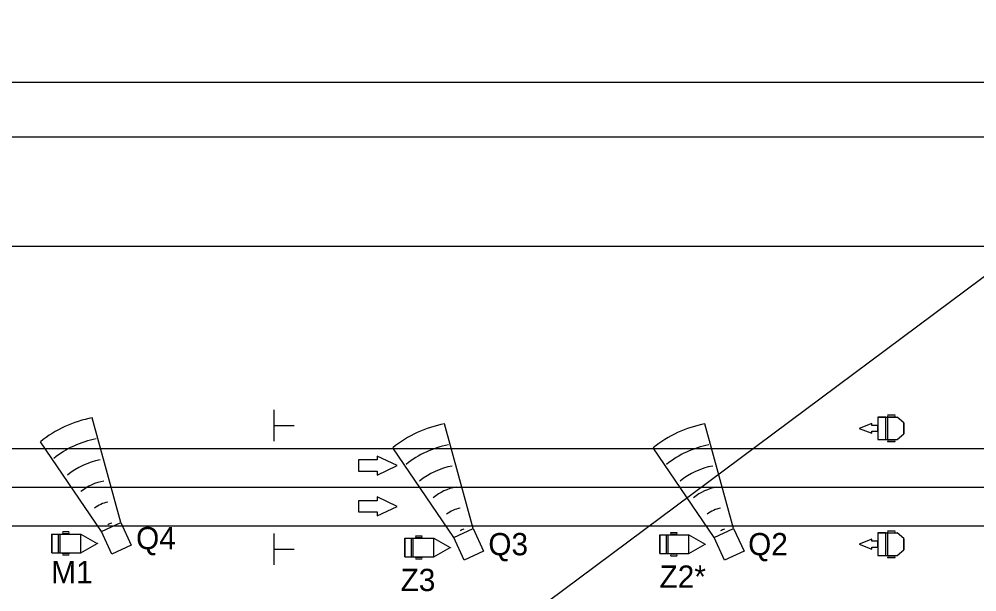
# Model space of a CAD drawing. Extents: x 1379436 to 1387057, y 792703 to 795604.
# Drawn here: x 1381631 to 1382289, y 794533 to 794926 of the extents above; entities that cross this region are included whole.
import ezdxf

# ---------------------------------------------------------------- set-up
doc = ezdxf.new("R2010")
doc.units = 0
for name, color, linetype in [('Black Area Fill Shapes', 7, 'Continuous'), ('Default', 7, 'Continuous'), ('DEV BORDER CELL', 7, 'Continuous'), ('DEV CMS PLAN VIEW CELL', 7, 'Continuous'), ('DEV DIRECTION OF TRAFFIC FLOW ARROW CELL', 7, 'Continuous'), ('Prop Mkg Skp Wht', 7, 'Continuous'), ('Prop Mkg Solid White Lane Line', 7, 'Continuous'), ('Prop Mkg Solid Yellow Edge Line', 7, 'Continuous'), ('Scratch_Level_0', 7, 'Continuous'), ('Sheet Plot Border Outside CELL', 7, 'Continuous'), ('TCP Linework', 7, 'Continuous'), ('Text', 7, 'Continuous')]:
    doc.layers.add(name, color=color, linetype=linetype)

msp = doc.modelspace()

# ---------------------------------------------------------------- linework, layer by layer
at = {"layer": 'Black Area Fill Shapes'}
for points in [[(1381694.77, 794558.48), (1381687.61, 794574.02), (1381700.92, 794580.15), (1381708.08, 794564.61)], [(1381936.61, 794554.34), (1381929.44, 794569.88), (1381942.75, 794576.02), (1381949.92, 794560.48)], [(1382115.43, 794554.34), (1382108.26, 794569.88), (1382121.57, 794576.02), (1382128.74, 794560.48)]]:
    msp.add_lwpolyline(points, close=True, dxfattribs=at)
at = {"layer": 'Default'}
msp.add_line((1379547.85, 792703.35), (1383441.11, 795604.31), dxfattribs=at)
at = {"layer": 'DEV BORDER CELL'}
msp.add_lwpolyline([(1382570.75, 794844.71), (1380320.75, 794844.71), (1380320.75, 793269.71), (1382570.75, 793269.71)], close=True, dxfattribs=at)
at = {"layer": 'DEV CMS PLAN VIEW CELL'}
for p, q in [((1381653.49, 794572.32), (1381653.49, 794559.39)), ((1381653.49, 794572.3), (1381673.49, 794572.3)), ((1381653.49, 794559.38), (1381653.49, 794572.3)), ((1381658.16, 794559.38), (1381658.16, 794572.3)), ((1381659.23, 794559.38), (1381659.23, 794572.3)), ((1381661.04, 794573.94), (1381665.17, 794573.94)), ((1381661.04, 794572.71), (1381665.17, 794572.71)), ((1381673.49, 794559.39), (1381673.49, 794572.3)), ((1381673.49, 794572.3), (1381684.67, 794565.85)), ((1381895.85, 794569.51), (1381895.85, 794556.59)), ((1381895.85, 794569.5), (1381915.85, 794569.5)), ((1381895.85, 794556.58), (1381895.85, 794569.5)), ((1381900.53, 794556.58), (1381900.53, 794569.5)), ((1381901.6, 794556.58), (1381901.6, 794569.5)), ((1381903.41, 794571.14), (1381907.54, 794571.14)), ((1381903.41, 794569.91), (1381907.54, 794569.91)), ((1381915.85, 794556.59), (1381915.85, 794569.5)), ((1381915.85, 794569.5), (1381927.04, 794563.04)), ((1382070.86, 794571.79), (1382070.86, 794558.87)), ((1382070.86, 794571.78), (1382090.86, 794571.78)), ((1382070.86, 794558.86), (1382070.86, 794571.78)), ((1382075.54, 794558.86), (1382075.54, 794571.78)), ((1382076.61, 794558.86), (1382076.61, 794571.78)), ((1382078.41, 794573.42), (1382082.54, 794573.42)), ((1382078.41, 794572.19), (1382082.54, 794572.19)), ((1382090.86, 794558.87), (1382090.86, 794571.78)), ((1382090.86, 794571.78), (1382102.04, 794565.33)), ((1381673.49, 794559.39), (1381684.67, 794565.85)), ((1381915.85, 794556.59), (1381927.04, 794563.04)), ((1382090.86, 794558.87), (1382102.04, 794565.33)), ((1381653.49, 794559.39), (1381673.49, 794559.39)), ((1381661.04, 794559.13), (1381665.17, 794559.13)), ((1381661.04, 794557.96), (1381665.17, 794557.96)), ((1381895.85, 794556.59), (1381915.85, 794556.59)), ((1381903.41, 794556.33), (1381907.54, 794556.33)), ((1382070.86, 794558.87), (1382090.86, 794558.87)), ((1382078.41, 794558.61), (1382082.54, 794558.61)), ((1382078.41, 794557.43), (1382082.54, 794557.43)), ((1381903.41, 794555.15), (1381907.54, 794555.15))]:
    msp.add_line(p, q, dxfattribs=at)
for centre in [(1381684.78, 794565.83), (1381927.15, 794563.03), (1382102.16, 794565.31)]:
    msp.add_circle(centre, 0.114, dxfattribs=at)
for centre, start, end in [((1381661.79, 794573.3), 142.08835, 217.91165), ((1381664.42, 794573.3), 322.08835, 37.91165), ((1381904.16, 794570.5), 142.08835, 217.91165), ((1381906.78, 794570.5), 322.08835, 37.91165), ((1382079.17, 794572.78), 142.08835, 217.91165), ((1382081.79, 794572.78), 322.08835, 37.91165), ((1381661.79, 794558.54), 142.08835, 217.91165), ((1381664.42, 794558.54), 322.08835, 37.91165), ((1381904.16, 794555.74), 142.08835, 217.91165), ((1381906.78, 794555.74), 322.08835, 37.91165), ((1382079.17, 794558.02), 142.08835, 217.91165), ((1382081.79, 794558.02), 322.08835, 37.91165)]:
    msp.add_arc(centre, 0.954, start, end, dxfattribs=at)
at = {"layer": 'DEV DIRECTION OF TRAFFIC FLOW ARROW CELL'}
for p, q in [((1381876.83, 794623.12), (1381864.05, 794623.12)), ((1381864.05, 794623.12), (1381864.05, 794615.41)), ((1381890.59, 794619.25), (1381876.83, 794625.74)), ((1381876.83, 794625.74), (1381876.83, 794623.12)), ((1381864.05, 794615.41), (1381876.82, 794615.4)), ((1381876.82, 794612.78), (1381890.59, 794619.25)), ((1381876.82, 794615.4), (1381876.82, 794612.78)), ((1381876.83, 794595.16), (1381864.05, 794595.17)), ((1381864.05, 794595.17), (1381864.05, 794587.46)), ((1381890.59, 794591.3), (1381876.83, 794597.79)), ((1381876.83, 794597.79), (1381876.83, 794595.16)), ((1381876.82, 794584.83), (1381890.59, 794591.3)), ((1381864.05, 794587.46), (1381876.82, 794587.45)), ((1381876.82, 794587.45), (1381876.82, 794584.83))]:
    msp.add_line(p, q, dxfattribs=at)
at = {"layer": 'Prop Mkg Skp Wht'}
msp.add_line((1381406.39, 794604.5), (1382495.75, 794604.51), dxfattribs=at)
at = {"layer": 'Prop Mkg Solid White Lane Line'}
msp.add_line((1381406.39, 794577.88), (1382495.75, 794577.88), dxfattribs=at)
at = {"layer": 'Prop Mkg Solid Yellow Edge Line'}
msp.add_line((1381406.39, 794631.12), (1382495.75, 794631.12), dxfattribs=at)
at = {"layer": 'Scratch_Level_0'}
msp.add_lwpolyline([(1382495.75, 794769.71), (1380395.75, 794769.71), (1380395.75, 793344.71), (1381714.03, 793344.71), (1381714.03, 793522.11), (1382495.75, 793522.11)], close=True, dxfattribs=at)
at = {"layer": 'Sheet Plot Border Outside CELL'}
msp.add_lwpolyline([(1380076.25, 793232.21), (1382608.25, 793232.21), (1382608.25, 794882.21), (1380076.25, 794882.21)], close=True, dxfattribs=at)
at = {"layer": 'TCP Linework'}
for p, q in [((1381805.89, 794657.59), (1381805.89, 794636.03)), ((1382227.36, 794654.14), (1382232.29, 794654.14)), ((1382216.45, 794648.25), (1382207.75, 794644.86)), ((1382216.45, 794646.88), (1382216.45, 794648.25)), ((1382220.49, 794652.57), (1382233.92, 794652.57)), ((1382220.49, 794652.57), (1382220.49, 794637.15)), ((1382226.07, 794652.57), (1382220.49, 794652.57)), ((1382220.49, 794652.57), (1382220.49, 794637.15)), ((1382226.07, 794637.15), (1382226.07, 794652.57)), ((1382227.35, 794637.14), (1382227.35, 794652.57)), ((1382227.36, 794652.74), (1382232.29, 794652.74)), ((1382238.39, 794648.71), (1382233.92, 794652.57)), ((1382238.39, 794641), (1382238.39, 794648.71)), ((1382238.39, 794648.71), (1382238.39, 794644.86)), ((1381805.89, 794646.72), (1381819.86, 794646.72)), ((1382207.75, 794644.86), (1382216.45, 794641.47)), ((1382220.49, 794646.87), (1382216.45, 794646.88)), ((1382216.45, 794641.47), (1382216.45, 794642.84)), ((1382216.45, 794642.84), (1382220.49, 794642.84)), ((1382220.49, 794642.84), (1382220.49, 794646.87)), ((1382233.92, 794637.15), (1382238.39, 794641)), ((1382238.39, 794644.86), (1382238.39, 794641)), ((1382220.49, 794637.15), (1382233.92, 794637.15)), ((1382220.49, 794637.15), (1382226.07, 794637.15)), ((1382227.36, 794636.96), (1382232.29, 794636.96)), ((1382232.29, 794635.56), (1382227.36, 794635.56)), ((1381805.89, 794572.74), (1381805.89, 794551.17)), ((1382216.45, 794568.68), (1382207.75, 794565.3)), ((1382216.45, 794567.31), (1382216.45, 794568.68)), ((1382220.49, 794573), (1382233.92, 794573)), ((1382220.49, 794573), (1382220.49, 794557.58)), ((1382226.07, 794573), (1382220.49, 794573)), ((1382220.49, 794573), (1382220.49, 794557.58)), ((1382226.07, 794557.58), (1382226.07, 794573)), ((1382227.35, 794557.57), (1382227.35, 794573)), ((1382227.36, 794574.58), (1382232.29, 794574.58)), ((1382227.36, 794573.18), (1382232.29, 794573.18)), ((1382238.39, 794569.15), (1382233.92, 794573)), ((1382238.39, 794561.44), (1382238.39, 794569.15)), ((1382238.39, 794569.15), (1382238.39, 794565.29)), ((1382207.75, 794565.3), (1382216.45, 794561.91)), ((1382220.49, 794567.31), (1382216.45, 794567.31)), ((1382216.45, 794561.91), (1382216.45, 794563.28)), ((1382216.45, 794563.28), (1382220.49, 794563.28)), ((1382220.49, 794563.28), (1382220.49, 794567.31)), ((1382238.39, 794565.29), (1382238.39, 794561.44)), ((1381805.89, 794561.87), (1381819.86, 794561.87)), ((1382220.49, 794557.58), (1382233.92, 794557.58)), ((1382220.49, 794557.58), (1382226.07, 794557.58)), ((1382227.36, 794557.4), (1382232.29, 794557.4)), ((1382232.29, 794556), (1382227.36, 794556)), ((1382233.92, 794557.58), (1382238.39, 794561.44))]:
    msp.add_line(p, q, dxfattribs=at)
for centre, start, end in [((1382228.26, 794653.44), 142.08835, 217.91165), ((1382231.39, 794653.44), 322.08835, 37.91165), ((1382228.26, 794636.26), 142.08835, 217.91165), ((1382231.39, 794636.26), 322.08835, 37.91165), ((1382228.26, 794573.88), 142.08835, 217.91165), ((1382231.39, 794573.88), 322.08835, 37.91165), ((1382228.26, 794556.7), 142.08835, 217.91165), ((1382231.39, 794556.7), 322.08835, 37.91165)]:
    msp.add_arc(centre, 1.14, start, end, dxfattribs=at)
at = {"layer": 'Text'}
for p, q in [((1381700.92, 794580.15), (1381681.28, 794652.05)), ((1381942.75, 794576.02), (1381923.11, 794647.91)), ((1382121.57, 794576.02), (1382101.93, 794647.91)), ((1381687.61, 794574.02), (1381645.72, 794635.66)), ((1381929.44, 794569.88), (1381887.55, 794631.52)), ((1382108.26, 794569.88), (1382066.37, 794631.52))]:
    msp.add_line(p, q, dxfattribs=at)
for centre, radius in [((1381695.72, 794573.93), 79.44), ((1381937.56, 794569.79), 79.44), ((1382116.38, 794569.79), 79.44), ((1381695.72, 794573.93), 64.74), ((1381937.56, 794569.79), 64.74), ((1382116.38, 794569.79), 64.74), ((1381695.72, 794573.93), 50.04), ((1381937.56, 794569.79), 50.04), ((1382116.38, 794569.79), 50.04), ((1381695.72, 794573.93), 35.34), ((1381937.56, 794569.79), 35.34), ((1382116.38, 794569.79), 35.34), ((1381695.72, 794573.93), 20.63), ((1381937.56, 794569.79), 20.63), ((1382116.38, 794569.79), 20.63), ((1381695.72, 794573.93), 5.93), ((1381937.56, 794569.79), 5.93), ((1382116.38, 794569.79), 5.93)]:
    msp.add_arc(centre, radius, 100.47314, 129.0092, dxfattribs=at)

# ---------------------------------------------------------------- texts
for s, p in [('Q4', (1381711.39, 794561.83)), ('Q3', (1381953.21, 794557.7)), ('Q2', (1382131.55, 794557.7)), ('M1', (1381653.15, 794538.48)), ('Z2*', (1382070.74, 794535.41)), ('Z3', (1381892.98, 794533.13))]:
    msp.add_text(s, height=15.29, dxfattribs=at).set_placement(p)

doc.saveas('drawing.dxf')
